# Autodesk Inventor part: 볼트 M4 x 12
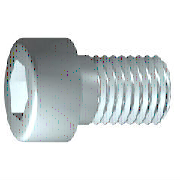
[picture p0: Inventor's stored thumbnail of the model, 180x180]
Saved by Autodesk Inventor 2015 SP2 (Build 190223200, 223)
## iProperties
IsCustomPart: 0
Created: 2012-02
Part Number: 볼트 M4 x 12
Material: 강철, 연강
Description: 6각 소켓 머리 캡 나사
Document SubType Name: Modeling
Standard: ISO 4762
Designer: mduedu
Standard Revision: Fourth edition 2004-03-01
Standards Organization: ISO
Language: ko-KR
Size Designation: M4 x 12
Categories: <MemberInstance><Categories><Category DisplayName="조임쇠" InternalName="e4da775c-781d-43d5-af7c-5136215cf5a6" Mnemonic="FSTN"><Category DisplayName="볼트" InternalN
Density: 7.75 g/cm^3
Appearance: 강철
Author: mduedu
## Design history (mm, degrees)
sketch "스케치1"
  geometry: L1 (-1, 0)-(12, 0); L2 (12, 0)-(12, 2); L3 (12, 2)-(1.75, 2); L4 (1.75, 2)-(1.32, 2); L5 (1.32, 2)-(0, 2); L6 (0, 2)-(0, 3.5); L7 (0, 3.5)-(-4, 3.5); L8 (-4, 3.5)-(-4, 1.732); L9 (-4, 1.732)-(-2, 1.732); L10 (-2, 1.732)-(-1, 0); L11 (-7.2, 0)-(15.2, 0) reference; L12 (0, -0.7)-(0, 4.2) reference; L13 (1.75, 2)-(0, 2)
  constraints: 22 end point, 6 parallel, 2 collinear, 2 perpendicular, 1 horizontal, 1 point on line
  dimensions: "d1" = 10.25 distance from line of L3.end L2 (= GEL); "d2" = 0.42952 distance of L4.end L3.end (computed from GAL); "d3" = 4 distance between parallel lines of L8 L6 (= KOH); "d4" = 2 distance of L8.end L9.end (= INTI); "d5" = 60 deg angle of L10 L1; "d6" = 4 diameter of L3 L1 (= GD); "d7" = 4 diameter of L5 L1 (= BDM); "d8" = 3.4641 diameter of L9 L1 (= 1.1547 x SW); "d9" = 7 diameter of L7 L1 (= KOD); "d26" = 12 distance between parallel lines of L12 L2 (= NLG)
revolve "본체" sketch "스케치1" stored, may be unused: angle "d10" = 90 deg
sketch "스케치2"
  geometry: L1 (0, -4.9)-(0, 4.9) reference; L2 (-4.9, 0)-(4.9, 0) reference; L3 (1.732, 0)-(0.866, -1.5); L4 (0.866, -1.5)-(-0.866, -1.5); L5 (-0.866, -1.5)-(-1.732, 0); L6 (-1.732, 0)-(-0.866, 1.5); L7 (-0.866, 1.5)-(0.866, 1.5); L8 (0.866, 1.5)-(1.732, 0); 2 further points
  constraints: 12 end point, 1 coincident, 1 horizontal alignment, 1 point on line, 12 other
extrude "슬롯" join sketch "스케치2" stored distance "d11" = 10; taper "d12" = 0 deg
workplane "Work Plane1"
fillet "Fillet2" dims "d30" = 0.1 (= R)
body "Solid1"
fillet "모깎기1" dims "d17" = 0.4 (= RR)
feature "스레드" dims "d13" = 10.25 (= GEL), "d14" = 0
chamfer "모따기1" distance "d15" = 0.42941 (= -0.5 x SPD + 0.5 x GD); stored, may be unused: second distance "d16" = 0.42941 (= GUL), angle "d27" = 45 deg
other parameters: "GD" = 4 [user parameter; used in 2 equation terms], "NLG" = 12 [user parameter; used in 1 equation term], "GEL" = 10.25 [user parameter; used in 2 equation terms], "KOD" = 7 [user parameter; used in 1 equation term], "KOH" = 4 [user parameter; used in 1 equation term], "INTI" = 2 [user parameter; used in 1 equation term], "GAL" = 0.42941 (= 0.61345 x PTC) [user parameter; used in 1 equation term], "GUL" = 0.42941 (= 0.61345 x PTC) [user parameter; used in 1 equation term], "BDM" = 4 (= NND) [user parameter; used in 1 equation term], "SW" = 3 [user parameter; used in 2 equation terms], "RR" = 0.4 [user parameter; used in 1 equation term], "SPD" = 3.14117 (= NND - 1.2269 x PTC) [user parameter; used in 1 equation term], "d19" = 0, "d28" = 0, "d29" = 0, "R" = 0.1 [user parameter; used in 1 equation term], "TOA" = 30 deg [user parameter], "GD1" = 3.14117 (= THREADDIA - 1.2269 x PTC) [user parameter], "THREADDIA" = 4 [user parameter; used in 1 equation term], "FAWI" = 45 deg [user parameter], "TPU" = 14.28571 (computed from PTC) [user parameter], "PTC" = 0.7 [user parameter; used in 5 equation terms], "NND" = 4 [user parameter; used in 2 equation terms], "E0" = 3.465 (= 1.155 x SW) [user parameter]
